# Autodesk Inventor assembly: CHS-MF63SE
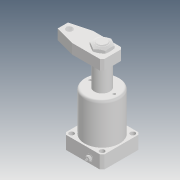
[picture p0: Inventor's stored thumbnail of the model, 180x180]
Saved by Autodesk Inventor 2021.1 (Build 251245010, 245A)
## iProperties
Created: 2019-05
Part Number: CHS-MF63SE
Description: STEP AP203
Document SubType Name: Assembly
Designer: user
Title: chs-mf63s-e_asm.STEP
Revision Number: ÈÎºÎ
Sending System: SolidWorks 2017
Preprocessor: SwSTEP 2.0
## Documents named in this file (9)
- D:\Vault_2016\Projekty\Clamptek\Hydraulic\CHS\CHS-63\Inventor\CHS-MF63SE\CHS-MF63SE.iam
- D:\Vault_2016\Projekty\Clamptek\Hydraulic\CHS\CHS-63\Inventor\CHS-MF63SE\CHS-MF63-03-E_1.ipt
- D:\Vault_2016\Projekty\Clamptek\Hydraulic\CHS\CHS-63\Inventor\CHS-MF63SE\CHS-63S-02-E_1.ipt
- D:\Vault_2016\Projekty\Clamptek\Hydraulic\CHS\CHS-63\Inventor\CHS-MF63SE\CHS-63S-01_5.ipt
- D:\Vault_2016\Projekty\Clamptek\Hydraulic\CHS\CHS-63\Inventor\CHS-MF63SE\M24_5.ipt
- D:\Vault_2016\Projekty\Clamptek\Hydraulic\CHS\CHS-63\Inventor\CHS-MF63SE\CHS-TXF-01_3.ipt
- D:\Vault_2016\Projekty\Clamptek\Hydraulic\CHS\CHS-63\Inventor\CHS-MF63SE\CHS-MF40-TXF-03_3.ipt
- D:\Vault_2016\Projekty\Clamptek\Hydraulic\CHS\CHS-63\Inventor\CHS-MF63SE\CHS-MF40-TXF-02_3.ipt
- D:\Vault_2016\Projekty\Clamptek\Hydraulic\CHS\CHS-63\Inventor\CHS-MF63SE\M6_3.ipt
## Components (8 placed, 8 different names)
1. CHS-MF63-03-E_1_1
2. CHS-63S-02-E_1_2
3. CHS-63S-01_5_3
4. M24_5_4
5. CHS-TXF-01_3_5
6. CHS-MF40-TXF-03_3_6
7. CHS-MF40-TXF-02_3_7
8. M6_3_8
